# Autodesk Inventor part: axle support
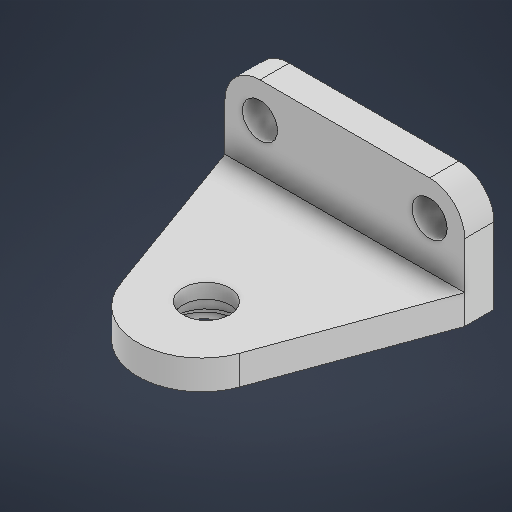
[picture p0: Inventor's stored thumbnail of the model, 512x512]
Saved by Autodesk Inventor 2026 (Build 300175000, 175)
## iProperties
Created: 2025-05
Part Number: axle support
Material: Generic
Document SubType Name: Modeling
Designer: Ritul Kumari
Density: 1 g/cm^3
Appearance: Default
Author: Ritul Kumari
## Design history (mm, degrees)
node "3D Sketch1"
node "3D Sketch2"
sketch "Sketch1"
  geometry: L1 (-16.32, 0)-(-16.32, 965.2); L2 (-16.32, 965.2)-(2066.48, 965.2); L3 (2066.48, 965.2)-(2066.48, 0); L4 (2066.48, 0)-(0, 0); L5 (2066.48, 0)-(-16.32, 0); 1 further point
  constraints: 10 end point, 2 horizontal, 2 perpendicular, 1 vertical
  dimensions: "d0" = 965.2 distance of L1.start L1.end; "d1" = 2082.8 distance of L1.end L2.end
extrude "Extrusion1" new body sketch "Sketch1" distance "d2" = 254; taper "d3" = 0 deg
fillet "Fillet1" dims "d4" = 304.8
sketch "Sketch2"
  geometry: C1 r 152.4 at (288.48, 660.4); A1 r 304.8 centre (288.48, 660.4) between (288.48, 965.2) and (-16.32, 660.4) reference; 1 further point
  constraints: 1 centre point, 1 coincident
  dimensions: "d5" = 304.8 diameter of C1
hole "Hole1" sketch "Sketch2" at (288.48, 660.4) diameter "d6" = 304.8; stored, may be unused: countersink angle "d10" = 82 deg, drill point angle "d12" = 118 deg; dims "d7" = 19.05, "d8" = 9.525, "d9" = 6.35, "d11" = 25.4
sketch "Sketch3"
  geometry: C1 r 152.4 at (1761.68, 660.4); A1 r 304.8 centre (1761.68, 660.4) between (2066.48, 660.4) and (1761.68, 965.2) reference; 1 further point
  constraints: 1 centre point, 1 coincident
  dimensions: "d13" = 304.8 diameter of C1
hole "Hole2" sketch "Sketch3" at (1761.68, 660.4) diameter "d14" = 304.8; stored, may be unused: countersink angle "d18" = 82 deg, drill point angle "d20" = 118 deg; dims "d15" = 19.05, "d16" = 9.525, "d17" = 6.35, "d19" = 25.4
node "3D Sketch3"
sketch "Sketch4"
  geometry: L1 (16.32, 254)-(-2066.48, 254) reference; L2 (16.32, 254)-(-1025.08, 254); L3 (-1025.08, 254)-(-1025.08, 1473.2); L4 (16.32, 254)-(-504.919, 1686.092); L5 (16.32, 254)-(1540.32, 254); L6 (-2066.48, 254)-(-1545.242, 1686.092); L7 (-2066.48, 254)-(-542.48, 254); A1 r 553.544 centre (-1025.08, 1496.768) between (-504.919, 1686.092) and (-1545.242, 1686.092); 1 further point
  constraints: 12 end point, 2 equal length, 2 horizontal, 2 point on circle, 1 centre point, 1 midpoint, 1 perpendicular, 1 tangent
  dimensions: "d21" = 1219.2 distance of L2.end L3.end; "d22" = 1524 distance of L1.start L4.end; "d23" = 110 deg angle of L5 L4; "d24" = 1524 distance of L1.end L6.end; "d25" = 70 deg angle of L7 L6
extrude "Extrusion2" join sketch "Sketch4" distance "d26" = 254; taper "d27" = 0 deg
sketch "Sketch5"
  geometry: 3 further points
  constraints: 1 coincident
sketch "Sketch6"
  geometry: L1 (-2066.48, 0)-(-2066.48, 254) reference; L2 (-2066.48, 0)-(-1025.08, 0); L3 (-1609.28, 0)-(-1914.08, 0) reference; L4 (-1025.08, 0)-(-1025.08, 1473.2); C1 r 203.2 at (-1025.08, 1473.2); C2 r 279.4 at (-1025.08, 1473.2); C3 r 431.8 at (-1025.08, 1473.2); 1 further point
  constraints: 4 end point, 3 centre point, 3 coincident, 1 collinear, 1 perpendicular
  dimensions: "d28" = 1041.4 distance of L1.start L2.end; "d29" = 1473.2 distance of L2.end L4.end; "d30" = 406.4 diameter of C1; "d31" = 558.8 diameter of C2; "d32" = 863.6 diameter of C3
extrude "Extrusion3" join sketch "Sketch6" distance "d33" = 50.8; taper "d34" = 0 deg
sketch "Sketch7"
  geometry: C1 r 279.4 at (-1025.08, 1473.2) reference; C2 r 203.2 at (-1025.08, 1473.2); 2 further points
  constraints: 1 centre point, 1 coincident
  dimensions: "d35" = 406.4 diameter of C2
hole "Hole3" sketch "Sketch7" at (-1010.281, 1441.398) diameter "d36" = 406.4; stored, may be unused: countersink angle "d40" = 82 deg, drill point angle "d42" = 118 deg; dims "d37" = 19.05, "d38" = 558.8, "d39" = 127, "d41" = 25.4
body "Solid1"
